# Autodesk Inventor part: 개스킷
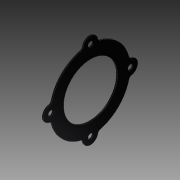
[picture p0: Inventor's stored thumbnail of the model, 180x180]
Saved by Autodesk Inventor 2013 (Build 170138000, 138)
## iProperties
Created: 2022-07
Part Number: 개스킷
Material: 황동, 연질 노란색
Document SubType Name: Modeling
Designer: mdu-01
Density: 1 g/cm^3
Author: mdu-01
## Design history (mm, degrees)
sketch "스케치1"
  geometry: C1 r 25 at (0, 0); C2 r 2.25 at (0, 37); C3 r 2.25 at (-37, 0); C4 r 2.25 at (0, -37); C5 r 2.25 at (37, 0); A1 r 7 centre (0, 37) between (6.969, 36.338) and (-6.969, 36.338); A2 r 7 centre (-37, 0) between (-36.338, 6.969) and (-36.338, -6.969); A3 r 7 centre (0, -37) between (-6.969, -36.338) and (6.969, -36.338); A4 r 7 centre (37, 0) between (36.338, -6.969) and (36.338, 6.969); A5 r 37 centre (0, 0) between (36.338, 6.969) and (6.969, 36.338); A6 r 37 centre (0, 0) between (-6.969, 36.338) and (-36.338, 6.969); A7 r 37 centre (0, 0) between (-36.338, -6.969) and (-6.969, -36.338); A8 r 37 centre (0, 0) between (6.969, -36.338) and (36.338, -6.969); 1 further point
  constraints: 17 point on circle, 13 centre point, 3 coincident, 1 vertical alignment, 26 other
  dimensions: "d4" = 14 diameter of A1; "d7" = 360 deg dimension on point (0, 0) A1.centre (derived); "d9" = 37 radius of A5; "d10" = 50 diameter of C1; "d13" = 4.5 diameter of C2; "d16" = 360 deg dimension on point (0, 0) C2.centre (derived)
extrude "돌출2" new body sketch "스케치1" stored distance "d18" = 1; taper "d19" = 0 deg
fillet "모깎기1" dims "d20" = 3
node "솔리드2"
other parameters: "d0" = 74
